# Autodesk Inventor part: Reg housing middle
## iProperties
Shininess: 64.0
Angle Display Precision: 2
Document Length Units: 11272
Document Angle Units: 11279
Document Time Units: 11290
Document Mass Units: 11286
Document Length Units Precision: 3
Document Angle Units Precision: 2
Created: 2006-10
Part Number: Reg housing middle
Document SubType Name: Modeling
Designer: John Croya
Density: 1 g/cm^3
Density: 0.0
Volumn: 0.0
Area: 0.0
PropertySet Name: Model Information
Control State: 0
Master: False
Checked Out: False
Author: John Croya
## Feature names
1. Reg housing middle [Revolution]
2. Top section threads
3. Bottom section threads
